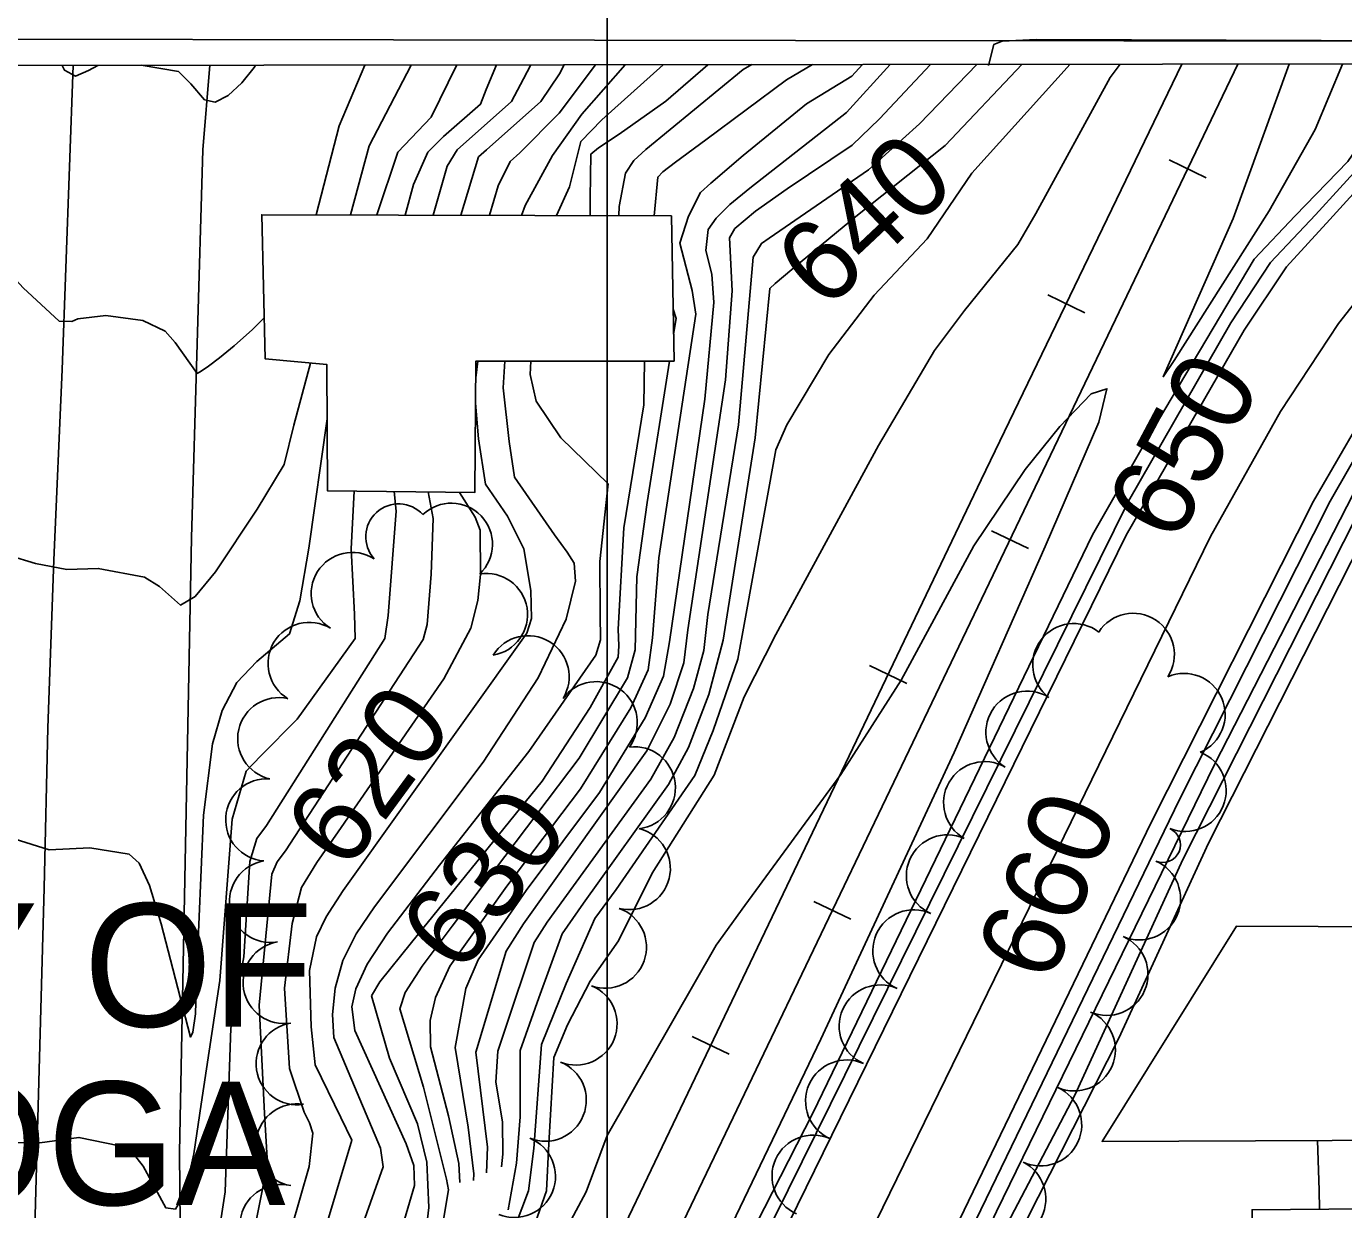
# Model space of a CAD drawing. Extents: x 79600 to 91800, y 75600 to 84400.
# Drawn here: x 85858.7 to 86179, y 83665.2 to 83953.1 of the extents above; entities that cross this region are included whole.
import ezdxf

# ---------------------------------------------------------------- set-up
doc = ezdxf.new("R2010")
doc.units = 0
for name, color, linetype in [('084-085$0$TI_CCLOGO', 7, 'Continuous'), ('084-090$0$BLDG', 7, 'Continuous'), ('084-090$0$BRIDGE', 7, 'Continuous'), ('084-090$0$GRID', 7, 'Continuous'), ('084-090$0$INDEX', 7, 'Continuous'), ('084-090$0$INDXLBL', 7, 'Continuous'), ('084-090$0$INTER', 7, 'Continuous'), ('084-090$0$ROAD', 7, 'Continuous'), ('084-090$0$RR', 7, 'Continuous'), ('084-090$0$TREES', 7, 'Continuous')]:
    doc.layers.add(name, color=color, linetype=linetype)

# ---------------------------------------------------------------- blocks, each defined once
blk = doc.blocks.new('084-090$0$RRTICK100')
blk.add_line((0, -5), (0, 5))

msp = doc.modelspace()

# ---------------------------------------------------------------- linework, layer by layer
at = {"layer": '084-090$0$BLDG'}
for points in [[(86360.4, 83914.42), (86362.69, 83682.87), (86120.31, 83681.86), (86152.99, 83734.21), (86232.34, 83733.91), (86232.8, 83827.94), (86280.21, 83827.33), (86279.9, 83874.1), (86338.56, 83874.38), (86338.47, 83914.82)], [(86015.57, 83907), (85915.99, 83907.25), (85916.8, 83872.21), (85931.79, 83870.82), (85931.94, 83840.1), (85967.76, 83839.68), (85968.06, 83871.64), (86016.23, 83871.65)], [(86231.32, 83665.82), (86156.76, 83665.24), (86157.16, 83592.83), (86232.02, 83594.81)]]:
    msp.add_lwpolyline(points, close=True, dxfattribs=at)
at = {"layer": '084-090$0$BRIDGE'}
msp.add_lwpolyline([(86213.2, 83937.05), (86207.73, 83943.95), (85115.45, 83942.72), (85107.21, 83932.76)], dxfattribs=at)
at = {"layer": '084-090$0$GRID'}
msp.add_line((86000, 84000), (86000, 80000), dxfattribs=at)
at = {"layer": '084-090$0$INDEX'}
for points in [[(86092.71, 83943.58), (86093.97, 83948.62), (86096, 83949.43), (86104.31, 83949.9), (86196.68, 83949.51), (86208.24, 83948.65), (86211.29, 83945.52), (86208.86, 83942.26)], [(85927.86, 83871.18), (85923.8, 83856.1), (85921.41, 83846.49), (85914.84, 83835.63), (85904.71, 83820.36), (85899.77, 83814.39), (85896.18, 83812.31), (85891.1, 83816.8), (85887.45, 83819.08), (85876.22, 83821.22), (85868.6, 83820.98), (85861, 83822.42), (85854.6, 83824.37), (85846.1, 83828.48), (85835.95, 83836.16), (85812.6, 83862.14), (85800.31, 83875.38), (85788.04, 83885.62), (85775.38, 83893.36), (85746.94, 83905.93), (85732.43, 83912.59), (85720.06, 83920.39), (85711.17, 83929.62), (85702.73, 83943.38)], [(85952.3, 83943.66), (85942.08, 83924), (85937.55, 83907.2)], [(85997.11, 83943.71), (85988.26, 83931.95), (85978.73, 83922.32), (85976.35, 83920.18), (85973.48, 83914.26), (85971.35, 83907.11)], [(86100.87, 83943.83), (86082.18, 83924.12), (86060.86, 83907.11), (86046.91, 83895.62), (86040.83, 83890.51), (86039.5, 83889.32), (86035.96, 83852.95), (86028.17, 83803.78), (86024.68, 83790.51), (86019.7, 83777.69), (86014.9, 83768.63), (85994.22, 83739.8), (85989.03, 83732.32), (85983.38, 83716.78), (85978.8, 83703.95), (85978.77, 83687.85), (85977.91, 83676.54), (85975.9, 83665.17)], [(86186.25, 83943.92), (86186.73, 83941.3), (86190.08, 83931.27), (86191.3, 83928.64), (86192.24, 83926.24), (86190.33, 83922.2), (86175.68, 83906.06), (86165.1, 83894.55), (86154.8, 83879.2), (86126.16, 83829.29), (86023.08, 83619.04), (85992.37, 83550.33), (85983.65, 83531.19), (85981.67, 83525.04), (85979.42, 83503.33), (85998.17, 83479.04)], [(86195.45, 83943.93), (86195.94, 83940.58), (86197.34, 83935.95), (86203.18, 83927.65), (86203.86, 83924.23), (86200.78, 83913.23), (86195.91, 83903.92), (86177.79, 83880.76), (86163.66, 83859.35), (86146.63, 83828.96), (86046.67, 83624.12), (86027.36, 83580.35), (86008.93, 83531.08), (86006.56, 83525.26), (86004.96, 83520.01), (86004.5, 83515.27), (86005.24, 83510.79), (86007.11, 83506.27), (86013.8, 83496.71), (86022.71, 83487.89)], [(86049.9, 83943.77), (86043.59, 83940.08), (86023.98, 83925.46), (86016.59, 83920.05), (86013.47, 83917.71), (86012.27, 83916.39), (86011.38, 83907.01)], [(86016, 83884.29), (86016.71, 83882.01), (86016.11, 83878.2)], [(86015.08, 83871.65), (86009.69, 83837.23), (86007.17, 83819.17), (86006.74, 83801.38), (86004.91, 83794.57), (85993.17, 83775.1), (85962.25, 83734.17), (85954.94, 83724.5), (85950.88, 83718.08), (85949.55, 83714.06), (85955.3, 83695.02), (85960.9, 83672.67), (85961.38, 83670.1), (85958.92, 83655.63)], [(86183.41, 83857.81), (86171.66, 83837.6), (86132.22, 83759.41), (86082.32, 83655.87), (86061.58, 83611.99), (86045.14, 83571.39), (86039, 83554.3), (86033.67, 83538.01), (86028.86, 83522.99), (86027.64, 83518.71), (86027.5, 83516.12), (86030.91, 83511.63), (86037.86, 83506.02), (86045.33, 83501.21), (86051.49, 83499.09), (86079.42, 83499.33), (86091.41, 83499.39), (86104.84, 83497.21), (86120.32, 83493.27), (86201.43, 83455.42)], [(85964.04, 83839.72), (85967.89, 83833.71), (85969.08, 83830.53), (85969.16, 83819.75), (85968.53, 83813.43), (85966.85, 83806.66), (85960.22, 83794.33), (85934.53, 83757.18), (85929.4, 83749.72), (85925.6, 83743.59), (85923.38, 83734.82), (85921.48, 83719.09), (85922.71, 83699.57), (85926.3, 83688.92), (85927.62, 83686.35), (85928.41, 83683.87), (85927.49, 83675.76), (85920.92, 83652.91)]]:
    msp.add_lwpolyline(points, dxfattribs=at)
at = {"layer": '084-090$0$INTER'}
msp.add_line((85968.53, 83871.64), (85968.02, 83867.58), dxfattribs=at)
for points in [[(85916.57, 83882.19), (85913.75, 83879.31), (85909.28, 83875.39), (85905.68, 83872.43), (85903.04, 83870.42), (85901.28, 83869.19), (85900.24, 83868.65), (85894.94, 83876.15), (85892.51, 83878.91), (85887.1, 83881.54), (85878.1, 83882.77), (85871.27, 83881.94), (85869.82, 83881.26), (85866.74, 83881.35), (85857.97, 83889.48), (85844.82, 83903.75), (85833.79, 83917.65), (85819.8, 83943.51)], [(85876.11, 83943.57), (85873.89, 83942.36), (85870.65, 83940.95), (85868.01, 83942.37), (85867.46, 83943.56)], [(85914.42, 83943.62), (85914.1, 83943.05), (85911.13, 83939.36), (85907.79, 83936.23), (85904.61, 83934.64), (85902.06, 83935.21), (85898.75, 83939.1), (85895.72, 83942.11), (85886.69, 83943.59)], [(85941.03, 83943.65), (85934.82, 83928.83), (85929.19, 83907.22)], [(85963.42, 83943.67), (85957.19, 83931), (85949.1, 83922.43), (85943.99, 83907.18)], [(85973.03, 83943.68), (85970.58, 83937.69), (85969.19, 83934.1), (85960.17, 83926.31), (85956.37, 83922.46), (85952.85, 83914.63), (85950.81, 83907.16)], [(86062.08, 83943.78), (86059.46, 83940.96), (86048.45, 83934.21), (86033.04, 83921.66), (86025.19, 83914.95), (86022.68, 83912.63), (86019.71, 83906.86), (86017.65, 83900.29), (86020.59, 83888.81), (86021.48, 83883.04), (86012.51, 83823.78), (86010.97, 83804.36), (86009.94, 83796.56), (86005.72, 83787.29), (85993.51, 83767.59), (85975.58, 83743.95), (85961.74, 83724.49), (85958.23, 83716.88), (85956.94, 83711.25), (85957, 83704.85), (85961.36, 83688.03), (85963.87, 83676.48), (85964.17, 83671.83)], [(85981.37, 83943.69), (85979.58, 83940.29), (85976.73, 83934.77), (85963.52, 83923.02), (85961.04, 83919.07), (85957.62, 83907.15)], [(86182.41, 83943.92), (86182.76, 83942.38), (86184.29, 83936.75), (86185.36, 83931.69), (86185.35, 83927.93), (86180.04, 83920.17), (86167.27, 83906.95), (86157.26, 83896.45), (86130.65, 83851.72), (86117.97, 83829.42), (86049.98, 83688.72), (86016.57, 83623.3), (85974.95, 83536.57), (85971.17, 83529.01), (85964.75, 83509.7), (85960.97, 83494.48), (85960.29, 83489.66)], [(86068.74, 83943.79), (86058.19, 83932.1), (86034.63, 83913.73), (86029.82, 83909.75), (86026.45, 83906.45), (86024.51, 83903.69), (86023.98, 83898.51), (86025.44, 83892.8), (86025.91, 83885.88), (86023.71, 83862.42), (86015.12, 83803.32), (86013.62, 83795.04), (86009.22, 83784.89), (85998.06, 83766.68), (85980.24, 83742.89), (85968.56, 83725.99), (85965.62, 83719.03), (85963.03, 83704.68), (85966.17, 83685.35), (85967.57, 83673.98), (85967.43, 83672.3)], [(85989.54, 83943.7), (85988.41, 83941.55), (85983.84, 83934.82), (85970.65, 83923.03), (85968.65, 83921.32), (85964.41, 83907.13)], [(86078.57, 83943.8), (86066.15, 83930.56), (86059.55, 83924.16), (86043.7, 83913.57), (86036.04, 83908.09), (86030.98, 83903.88), (86029.67, 83901.62), (86030.35, 83888.71), (86028.72, 83867.1), (86019.6, 83806.26), (86018.63, 83798.28), (86015.31, 83788.16), (86009.63, 83776.81), (85979.58, 83734.74), (85975.38, 83728.1), (85968.03, 83703.56), (85970.9, 83680.41), (85970.64, 83674.22)], [(86184.8, 83943.92), (86188.25, 83931.02), (86189.28, 83928.36), (86189.91, 83926.64), (86172.17, 83907.2), (86161.27, 83895.59), (86151.61, 83880.92), (86126.69, 83837.61), (86019.83, 83621.17), (85983.73, 83543.32), (85979.3, 83533.88), (85976.93, 83528.05), (85973.13, 83509.97), (85971.37, 83502.17), (85971.32, 83498.99), (85972.23, 83496.79), (85977.4, 83494.6), (85981.3, 83492.26), (85996.39, 83473.33)], [(86089.85, 83943.81), (86075.94, 83929.37), (86063.49, 83918.16), (86039.38, 83901.56), (86037.47, 83900.26), (86035.49, 83896.96), (86031.88, 83856.11), (86024.47, 83809.97), (86023.44, 83801.24), (86020.99, 83792.02), (86016.21, 83780.09), (86010.56, 83769.92), (85985.37, 83735.19), (85982.21, 83730.21), (85974.9, 83708.44), (85973.41, 83703.76), (85972.86, 83696.25), (85974.51, 83686.59), (85974.58, 83678.72), (85974.23, 83675.66)], [(86112.56, 83943.84), (86088.66, 83917.39), (86077.74, 83901.38), (86064.89, 83887.71), (86053.86, 83873.24), (86043.61, 83856.12), (86040.98, 83850.1), (86033.29, 83807.61), (86031.75, 83799.16), (86025.7, 83781.76), (86021.26, 83770.86), (86002.11, 83743.14), (85996.93, 83736.1), (85989.99, 83720.23), (85984.01, 83705.45), (85982.11, 83680.15), (85980.8, 83669.84), (85975.97, 83656.96)], [(86004.35, 83943.72), (85993.77, 83931.68), (85986.67, 83921.68), (85980, 83909.46), (85979.1, 83907.09)], [(86124.7, 83943.85), (86122.29, 83940.59), (86104.15, 83907.57), (86099.84, 83899.97), (86086.87, 83883.93), (86079.56, 83874.24), (86065.95, 83851.09), (86040.96, 83805.14), (86033.28, 83790.02), (86025.97, 83770.92), (86010.89, 83747.1), (86002.72, 83730.63), (85995.84, 83720.8), (85990.35, 83710.2), (85986.97, 83702.26), (85985.8, 83681.35), (85985.2, 83669.86), (85982.42, 83661.98)], [(86013.58, 83943.73), (85998.65, 83930.34), (85993.54, 83925.03), (85990.83, 83914.07), (85987.67, 83907.07)], [(86024.41, 83943.74), (86014.22, 83934.89), (86002.89, 83926.87), (85997.86, 83923.53), (85996.01, 83922.01), (85995.85, 83911.26), (85995.84, 83907.05)], [(86035.11, 83943.75), (86033.03, 83942.53), (86009.4, 83923.09), (86006.44, 83920.4), (86004.44, 83917.34), (86002.9, 83909.28), (86002.83, 83907.03)], [(86178.73, 83943.91), (86178.73, 83943.84), (86172.11, 83927.94), (86160.94, 83908.19), (86137.82, 83871.75), (86135.17, 83867.85), (86152.19, 83906.36), (86165.76, 83943.9)], [(86212.67, 83937.72), (86212.82, 83936.55), (86223.43, 83931.81), (86226.04, 83931.03), (86228.27, 83930.32), (86229.88, 83929.55), (86230.66, 83928.17), (86228.94, 83921.28), (86215.58, 83891.24), (86146.14, 83754.4), (86124.37, 83706.93), (86099.19, 83657.23), (86094.82, 83649.05), (86090.33, 83639), (86087.83, 83631.1), (86087.04, 83622.72), (86087.55, 83620.67)], [(85975.09, 83871.64), (85974.68, 83865.12), (85976.13, 83852.05), (85977.43, 83843.43), (85987.14, 83829.4), (85990.25, 83825.16), (85991.97, 83822.48), (85992.24, 83818.14), (85989.97, 83808.86), (85983.2, 83794.59), (85969.82, 83774.11), (85943.38, 83738.88), (85938.97, 83732.36), (85935.7, 83725.83), (85933.82, 83719.12), (85933.19, 83712.68), (85933.52, 83707.14), (85944.88, 83680.22), (85945.48, 83675.63), (85936.27, 83649.67), (85933.26, 83637.12), (85932.31, 83634.96)], [(85981.37, 83871.64), (85981.2, 83868.41), (85982.68, 83861.92), (85988.69, 83852.96), (86000.19, 83841.81), (85998.18, 83822.86), (85998.25, 83810.12), (85998.31, 83803.86), (85997.21, 83800.08), (85980.93, 83776.67), (85959.23, 83749.04), (85946.56, 83732.52), (85941.64, 83724.94), (85938.89, 83718.99), (85937.9, 83714.56), (85938.6, 83708.85), (85951.12, 83681.27), (85952.92, 83675.98), (85953.1, 83671.12), (85949.9, 83660.13), (85942.07, 83642.15), (85938.41, 83636.38)], [(86009.01, 83871.65), (86008.89, 83861.03), (86004.01, 83831.05), (86002.65, 83806.44), (86002.77, 83802.41), (86002.6, 83799.62), (85995.79, 83787.35), (85984.15, 83769.45), (85952.36, 83730.22), (85944.66, 83720.63), (85942.69, 83717.26), (85947.02, 83702.09), (85953.85, 83686.12), (85956.12, 83676.81), (85956.56, 83665.77), (85955.47, 83656.12), (85953.87, 83650.83), (85941.51, 83635.53)], [(85945.5, 83485.76), (86001.86, 83602.33), (86051.93, 83706.74), (86084.32, 83776.43), (86106.49, 83826.51), (86119.5, 83856.77), (86121.47, 83864.93), (86117.63, 83863.68), (86110.02, 83855.73), (86101.62, 83845.3), (86089.15, 83826.68), (86071.48, 83794.06), (86056.75, 83771.07), (86033.4, 83739.23), (86026.45, 83729.59), (85999.93, 83683.31), (85994.87, 83669.61), (85969.83, 83622.77), (85966.42, 83616.73)], [(85967.97, 83861.45), (85968.66, 83852.72), (85970.36, 83841.68), (85975.69, 83833.89), (85979.67, 83825.98), (85981.38, 83815.81), (85981.59, 83809.05), (85980.46, 83805.49), (85935.73, 83742.84), (85931.61, 83736.44), (85929.27, 83731.64), (85927.58, 83723.39), (85927.97, 83709.75), (85928.93, 83700.44), (85935.23, 83687.7), (85937.84, 83682.13), (85930.24, 83656.71), (85926.77, 83644), (85925.46, 83632.46)], [(85931.85, 83857.62), (85927.4, 83826.11), (85925.26, 83813.37), (85922.75, 83805.27), (85914.78, 83798.61), (85909.95, 83793.47), (85906.35, 83786.68), (85903.98, 83778.51), (85901.8, 83761.21), (85900.13, 83721.29), (85899.84, 83712.88), (85899.18, 83708.43), (85898.64, 83707.24), (85894.32, 83723.8), (85891.52, 83734.76), (85888.69, 83744.13), (85886.18, 83749.5), (85883.75, 83751.69), (85874.17, 83753.24), (85864.25, 83752.77), (85831.7, 83762.97)], [(86185.64, 83854.86), (86175.75, 83837.6), (86139.13, 83765.04), (86084.65, 83652.45), (86067.06, 83614.94), (86050.4, 83573.81), (86042.85, 83552.99), (86038.2, 83538.78), (86034.4, 83526.69), (86032.69, 83519.5), (86032.78, 83517.3), (86035.29, 83513.89), (86042.15, 83509.25), (86050.41, 83504.36), (86055.05, 83502.89), (86085.11, 83503.61), (86099.36, 83502.46), (86111.8, 83499.8), (86121.14, 83497.45), (86202.32, 83458.57)], [(86187.86, 83851.91), (86147.62, 83773.54), (86094.64, 83664.77), (86072.64, 83618.17), (86065.23, 83601.53), (86052.26, 83567.8), (86042.72, 83539.57), (86040.07, 83530.97), (86038.17, 83522.49), (86038.18, 83520.68), (86040.98, 83517), (86052.39, 83509.37), (86056.97, 83507.18), (86079.04, 83507.31), (86092.58, 83507.43), (86107.76, 83504.99), (86116.78, 83502.84), (86243.98, 83442.72)], [(86188.72, 83846.79), (86139.95, 83750.38), (86113.69, 83693.12), (86095.54, 83658.47), (86075.07, 83614.78), (86058.85, 83574.07), (86048.6, 83544.46), (86046.45, 83537.87), (86045.45, 83533.21), (86046.79, 83524.29), (86047.93, 83521.13), (86049.44, 83518.84), (86054.3, 83515.71), (86065.06, 83511.37), (86070.28, 83510.45), (86085.39, 83511.66), (86101.48, 83510.38), (86115.15, 83507.52), (86119.9, 83506.38), (86257.24, 83439.09)], [(85938.46, 83840.02), (85937.73, 83826.01), (85938.51, 83810.11), (85938.67, 83804.15), (85924.58, 83784.57), (85915.74, 83775.6), (85912.21, 83771.88), (85908.8, 83760.19), (85905.78, 83721.01), (85901.25, 83690.91), (85899.46, 83678.86), (85897.35, 83669.41), (85894.99, 83665.35), (85892.63, 83665.7), (85887.18, 83675.8), (85884.8, 83678.81), (85881.37, 83680.77), (85871.54, 83682.82), (85862.05, 83681.47), (85842, 83681.76)], [(85948.15, 83839.91), (85948.63, 83835.18), (85946.68, 83809.74), (85945.93, 83804.15), (85917.15, 83758.68), (85914.8, 83755.51), (85913.06, 83749.97), (85911.64, 83726.77), (85908.42, 83709.38), (85907.08, 83669.58), (85904.54, 83653.24), (85903.76, 83630.08), (85900.72, 83603.78), (85899.92, 83596.09), (85899.29, 83590.15), (85898.68, 83586.71), (85892.41, 83591.97), (85886.02, 83594.77), (85879.69, 83596.2), (85873.67, 83597.06), (85868.5, 83596.71), (85863.99, 83593.51), (85860.9, 83593.56), (85856.57, 83591.89)], [(85956.41, 83839.81), (85957.63, 83833.33), (85957.2, 83819.78), (85956.2, 83807.61), (85955.19, 83803.9), (85921.71, 83752.56), (85919.72, 83749.86), (85918.41, 83746.87), (85915.32, 83715.02), (85916.67, 83688.65), (85917.37, 83676.42), (85912.95, 83653.97), (85911.56, 83646.43), (85911.8, 83614.42), (85911.77, 83607.99), (85903.54, 83566.98), (85900.94, 83526.54), (85899.05, 83517.36), (85898.66, 83502.93), (85897.54, 83494.85), (85894.72, 83489.88)], [(86173.18, 83665.37), (86173.11, 83669.96), (86172.65, 83682.08)]]:
    msp.add_lwpolyline(points, dxfattribs=at)
at = {"layer": '084-090$0$ROAD'}
for points in [[(85752.53, 83950.1), (86045.72, 83949.6), (86205.36, 83949.48), (86239.64, 83948.89), (86357.18, 83943.26), (86361.98, 83941.61), (86364.48, 83938.7), (86366.37, 83935.32), (86367.99, 83927.78), (86372, 83693.15), (86373.1, 83550.97), (86375.67, 83400.31), (86399.75, 83400.86), (86392.54, 83771.16), (86392.46, 83935.58), (86393.5, 83938.84), (86400.23, 83945.22)], [(85870.09, 83943.57), (85867.42, 83869.56), (85865.41, 83823.23), (85863.96, 83782.46), (85863.11, 83743.54), (85859.01, 83596.06), (85859.01, 83533.84), (85859.93, 83503.13), (85860.97, 83491.1), (85860.46, 83480.29), (85853.35, 83465.55)], [(85898.04, 83461.03), (85896.01, 83679.18), (85898.86, 83828.65), (85901.63, 83923.01), (85903.35, 83943.6)]]:
    msp.add_lwpolyline(points, dxfattribs=at)
at = {"layer": '084-090$0$RR'}
for points in [[(86153.28, 83943.88), (85933.9, 83485.8), (85758.12, 83119.71), (85690.49, 82979.78), (85674.9, 82948.29), (85659.44, 82919.26), (85642.77, 82887.91), (85628.81, 82863.07), (85611.2, 82832.49), (85591.44, 82800.8), (85571.68, 82769.57), (85544.13, 82730.24), (85511.37, 82685.91), (85471.43, 82634.57), (85256.44, 82378.02), (85218.73, 82334.88), (85191.53, 82306.51), (85164.47, 82279.53), (85141.37, 82258.31), (85109.84, 82229.74), (85084.12, 82208.03), (85052.41, 82183.17), (85018.39, 82157.2), (85000, 82144.89)], [(86139.68, 83943.87), (86090.93, 83842.75), (85923.18, 83492.02), (85725.74, 83083.88), (85678.84, 82986.92), (85656.12, 82942.7), (85643.25, 82917.41), (85629, 82890.71), (85615.33, 82867.42), (85596.8, 82836.67), (85573.71, 82798.77), (85557.74, 82774.06), (85536.59, 82743.44), (85505.99, 82699.75), (85477.03, 82661.95), (85312.39, 82465.02), (85221.12, 82358.37), (85190.73, 82324.72), (85165.51, 82299.46), (85143.33, 82278.71), (85113.8, 82251.24), (85078.9, 82221.26)]]:
    msp.add_lwpolyline(points, dxfattribs=at)
at = {"layer": '084-090$0$TREES'}
for centre, radius, start, end in [((85949.24, 83828.94), 7.98, 42.2422, 222.2422), ((85962.07, 83827.08), 10, 313.7542, 133.7542), ((85938.01, 83815.11), 10, 57.7977, 237.7977), ((85970.6, 83809.99), 10, 279.2979, 99.2979), ((85927.5, 83798.09), 10, 58.8265, 238.8265), ((86113.42, 83797.8), 10, 52.64, 232.64), ((86127.87, 83800.3), 10, 327.0099, 147.0099), ((85980.72, 83794.86), 10, 328.2526, 148.2526), ((86140.22, 83785.68), 10, 293.3418, 113.3418), ((85997.29, 83783.68), 10, 323.7452, 143.7452), ((86102.05, 83781.37), 10, 57.9923, 237.9923), ((85920.12, 83779.79), 10, 77.2383, 257.2383), ((86006.56, 83767.84), 10, 276.9385, 96.9385), ((86140.47, 83767.21), 10, 248.1861, 68.1861), ((86091.76, 83764.22), 10, 60.1046, 240.1046), ((85917.2, 83760.06), 10, 85.9489, 265.9489), ((86005.33, 83748.22), 10, 255.8639, 75.8639), ((86082.7, 83746.42), 10, 65.9045, 245.9045), ((86135.05, 83753.98), 4.3, 246.6528, 66.6528), ((85918.14, 83740.22), 10, 99.4783, 279.4783), ((86129.38, 83740.85), 10, 246.6528, 66.6528), ((85999.51, 83729.11), 10, 250.2697, 70.2697), ((86074.53, 83728.17), 10, 65.9045, 245.9045), ((86121.45, 83722.49), 10, 246.6528, 66.6528), ((85921.43, 83720.5), 10, 99.4783, 279.4783), ((85992.38, 83710.43), 10, 247.9898, 67.9898), ((86066.37, 83709.91), 10, 65.9045, 245.9045), ((86113.53, 83704.12), 10, 246.6528, 66.6528), ((85924.6, 83700.75), 10, 98.7206, 278.7206), ((85984.89, 83691.88), 10, 247.9898, 67.9898), ((86058.2, 83691.65), 10, 65.9045, 245.9045), ((86105.34, 83685.88), 10, 245.0127, 65.0127), ((85924.57, 83680.99), 10, 81.1334, 261.1334), ((85977.39, 83673.34), 10, 247.9898, 67.9898), ((86050.04, 83673.39), 10, 65.9045, 245.9045), ((86096.61, 83667.88), 10, 243.247, 63.247), ((85920.66, 83661.39), 10, 76.2699, 256.2699)]:
    msp.add_arc(centre, radius, start, end, dxfattribs=at)

# ---------------------------------------------------------------- block references
at = {"layer": '084-090$0$RR'}
for p, rotation in [((86141.08, 83918.41), -115.59038802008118), ((86111.57, 83885.56), -115.7383054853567), ((86097.89, 83828.22), -115.59038802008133), ((86068.29, 83795.41), -115.56116173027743), ((86054.69, 83738.03), -115.59038802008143), ((86025.14, 83705.2), -115.56116173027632)]:
    msp.add_blockref('084-090$0$RRTICK100', p, dxfattribs=dict(at, rotation=rotation))

# ---------------------------------------------------------------- texts
at = {"layer": '084-085$0$TI_CCLOGO'}
for s, p in [('COUNTY OF', (85692.18, 83709.73)), ('CUYAHOGA', (85692.18, 83666.37))]:
    msp.add_text(s, height=30, dxfattribs=at).set_placement(p)
at = {"layer": '084-090$0$INDXLBL'}
for s, rotation, p in [('640', 43.2529, (86052.94, 83883.59)), ('650', 62.0111, (86138.24, 83826.75)), ('620', 53.7353, (85936.58, 83747.05)), ('630', 52.8423, (85964.28, 83721.93)), ('660', 68.1907, (86107.71, 83719.84))]:
    msp.add_text(s, height=20, rotation=rotation, dxfattribs=at).set_placement(p)

doc.saveas('drawing.dxf')
